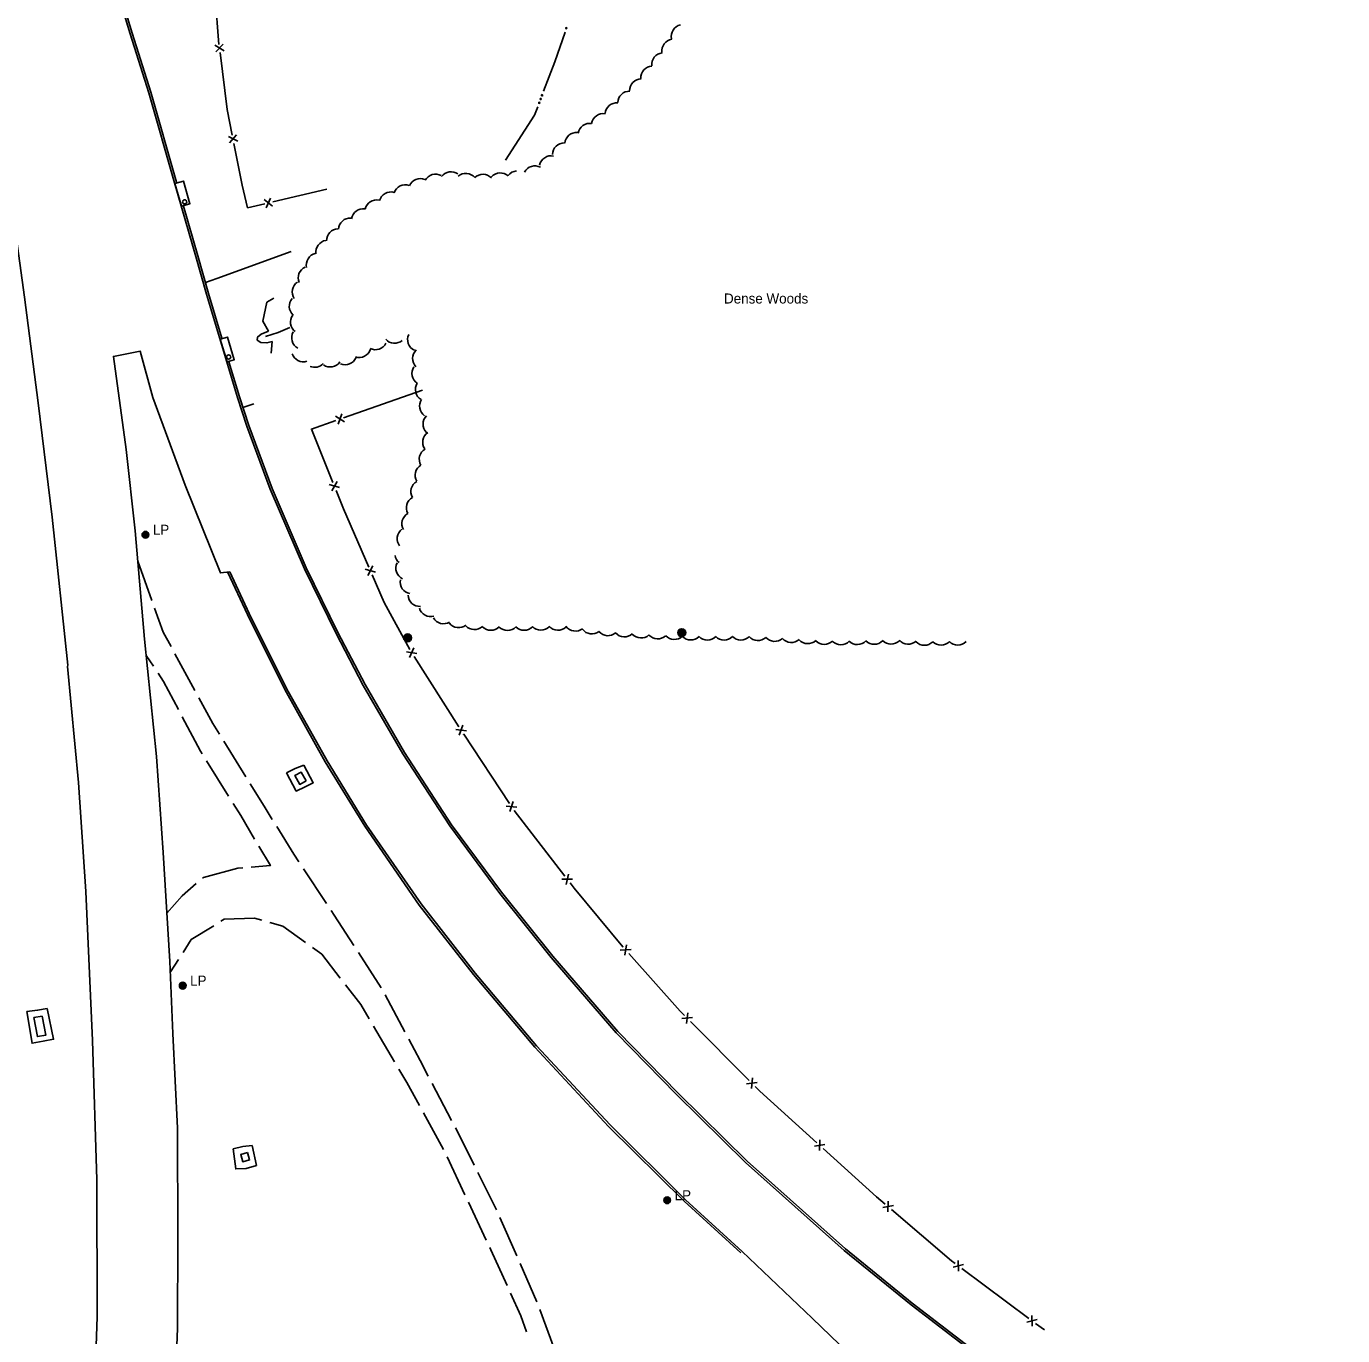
# Model space of a CAD drawing. Extents: x 2402803 to 2427059, y 6985292 to 6997652.
# Drawn here: x 2410720 to 2411350, y 6993013 to 6993640 of the extents above; entities that cross this region are included whole.
import ezdxf

# ---------------------------------------------------------------- set-up
doc = ezdxf.new("R2010")
doc.units = 0
for name, color, linetype in [('p_drainage conc drain', 7, 'Continuous'), ('p_drainage riprap', 7, 'Continuous'), ('p_drainage water', 7, 'Continuous'), ('p_road - paved curb', 7, 'Continuous'), ('p_road bridge end', 7, 'Continuous'), ('p_road dirt road', 7, 'Continuous'), ('p_structure fence', 7, 'Continuous'), ('p_structure general', 7, 'Continuous'), ('p_utility manhole', 7, 'Continuous'), ('p_veg woods', 7, 'Continuous')]:
    doc.layers.add(name, color=color, linetype=linetype)

msp = doc.modelspace()

# ---------------------------------------------------------------- linework, layer by layer
at = {"layer": 'p_drainage conc drain'}
for points in [[(2410835.86, 6993493.62), (2410833.12, 6993498.4), (2410835.12, 6993507.49), (2410838.52, 6993509.4)], [(2410837.63, 6993488.72), (2410837.17, 6993483.12)], [(2410852.84, 6993285.86), (2410857.34, 6993277.38), (2410853.46, 6993275.46), (2410849.22, 6993273.41), (2410844.47, 6993282.22)], [(2410844.47, 6993282.22), (2410848.72, 6993284.28), (2410852.84, 6993285.86)], [(2410720.19, 6993167.95), (2410722.65, 6993152.66), (2410727.99, 6993153.73), (2410732.93, 6993154.56), (2410729.81, 6993169.28)], [(2410729.81, 6993169.28), (2410725.31, 6993168.47), (2410720.19, 6993167.95)], [(2410830.17, 6993094.2), (2410825.12, 6993092.72), (2410820.22, 6993092.51), (2410819.02, 6993102.08), (2410823.61, 6993103.23), (2410827.99, 6993103.76)], [(2410827.99, 6993103.76), (2410830.17, 6993094.2)]]:
    msp.add_lwpolyline(points, dxfattribs=at)
at = {"layer": 'p_drainage riprap'}
for points in [[(2410805.65, 6993516.91), (2410811.16, 6993518.92), (2410846.77, 6993531.8)], [(2410823.66, 6993457.11), (2410828.9, 6993458.89)]]:
    msp.add_lwpolyline(points, dxfattribs=at)
at = {"layer": 'p_drainage water'}
for points in [[(2410967.69, 6993608.6), (2410973.01, 6993622.62), (2410977.91, 6993636.8)], [(2410949.42, 6993575.5), (2410963.32, 6993597.07), (2410964.86, 6993601.12)], [(2410834.39, 6993491.04), (2410840.51, 6993492.98), (2410846.15, 6993495.37)]]:
    msp.add_lwpolyline(points, dxfattribs=at)
for centre in [(2410978.57, 6993638.69), (2410966.25, 6993604.79), (2410966.93, 6993606.58), (2410965.57, 6993602.99)]:
    msp.add_circle(centre, 0.3, dxfattribs=at)
at = {"layer": 'p_road - paved curb'}
for points in [[(2410741.61, 6992826.02), (2410747.83, 6992895.57), (2410751.8, 6992961.6), (2410753.85, 6993021.62), (2410753.73, 6993087.24), (2410751.62, 6993154), (2410748.47, 6993225.36), (2410744.95, 6993277.46), (2410739.67, 6993333.06), (2410739.78, 6993333.65), (2410732.25, 6993404.63), (2410725.5, 6993459.29), (2410718.97, 6993509.93), (2410712.31, 6993558.83), (2410703.69, 6993610.23), (2410694.62, 6993664.96), (2410685.34, 6993713.02), (2410674.64, 6993766.89), (2410663.97, 6993813.71), (2410654.74, 6993854.5), (2410643.68, 6993898.31), (2410630.27, 6993950.34), (2410611.59, 6994020.31)], [(2410661.41, 6994010.21), (2410658.86, 6994008.83), (2410658.3, 6994005.38), (2410671.11, 6993965.12), (2410686.11, 6993913.59), (2410701.48, 6993863.45), (2410717.93, 6993809.81), (2410736.78, 6993747.65), (2410754.03, 6993691.08), (2410770.61, 6993636.29), (2410779.54, 6993608.03), (2410791.76, 6993564.95), (2410791.86, 6993564.61)], [(2410753.07, 6993690.79), (2410769.65, 6993635.99), (2410778.58, 6993607.74), (2410790.8, 6993564.67), (2410801.1, 6993529.39), (2410806.19, 6993511.31), (2410821.06, 6993461.9), (2410825.5, 6993448.18), (2410836.65, 6993417.97), (2410853.06, 6993379.91), (2410868.25, 6993348.87), (2410881.28, 6993323.93), (2410900.22, 6993291.3), (2410922.8, 6993256.76), (2410946.76, 6993224.37), (2410971.31, 6993193.78), (2411002.4, 6993157.69), (2411031.33, 6993128.1), (2411064.44, 6993095.5), (2411111.65, 6993053.47), (2411143.64, 6993027.42), (2411189.66, 6992992.15)], [(2410795.11, 6993553.47), (2410802.06, 6993529.67), (2410807.15, 6993511.59), (2410813.55, 6993490.32)], [(2410817.36, 6993378.43), (2410812.85, 6993377.9), (2410795.95, 6993419.89), (2410780.43, 6993461.86), (2410774.5, 6993484), (2410761.64, 6993481.57), (2410767.66, 6993436.99), (2410772.02, 6993397.98), (2410776.55, 6993346.19), (2410782.25, 6993289.92), (2410785.37, 6993243.96), (2410788.68, 6993191.83), (2410790.11, 6993157.32), (2410792.36, 6993112.02), (2410792.46, 6993059.64), (2410792.31, 6993016.31), (2410790.42, 6992966.33), (2410788.49, 6992929.02), (2410785.78, 6992887.8), (2410782.14, 6992848.18), (2410779.61, 6992824.88)], [(2410816.97, 6993478.96), (2410822.01, 6993462.2), (2410826.45, 6993448.51), (2410837.58, 6993418.34), (2410853.97, 6993380.33), (2410869.14, 6993349.32), (2410882.16, 6993324.41), (2410901.07, 6993291.82), (2410923.62, 6993257.33), (2410947.55, 6993224.98), (2410972.08, 6993194.42), (2411003.14, 6993158.37), (2411032.04, 6993128.81), (2411065.12, 6993096.23), (2411112.3, 6993054.23), (2411144.26, 6993028.2), (2411190.25, 6992992.96), (2411245.2, 6992955.15), (2411285.15, 6992929.75), (2411324.33, 6992906.35), (2411350.4, 6992892.78)], [(2411062.09, 6993052.3), (2411035.01, 6993077), (2410998.76, 6993112.87), (2410963.47, 6993150.82), (2410934.04, 6993185.62), (2410908.13, 6993218.83), (2410882, 6993256.56), (2410863.1, 6993287.37), (2410843.65, 6993322.06), (2410825.78, 6993357.96), (2410816.43, 6993378.01)], [(2411062.76, 6993053.04), (2411035.7, 6993077.73), (2410999.48, 6993113.57), (2410964.22, 6993151.48), (2410934.82, 6993186.25), (2410908.94, 6993219.42), (2410882.84, 6993257.11), (2410863.96, 6993287.88), (2410844.53, 6993322.53), (2410826.68, 6993358.39), (2410817.34, 6993378.43)], [(2411317.49, 6992824.55), (2411281.06, 6992855.57), (2411247.54, 6992884.91), (2411216.91, 6992910.99), (2411184.48, 6992939.55), (2411159.27, 6992962.45), (2411126.67, 6992991.89), (2411096.26, 6993021.03), (2411062.76, 6993053.04)]]:
    msp.add_lwpolyline(points, dxfattribs=at)
at = {"layer": 'p_road bridge end'}
for points in [[(2410794.18, 6993553.47), (2410791.01, 6993564.31), (2410795.12, 6993565.51), (2410798.29, 6993554.67)], [(2410816.04, 6993478.94), (2410812.8, 6993489.74), (2410816.24, 6993490.77), (2410819.48, 6993479.97)], [(2410853.86, 6993278.25), (2410851.51, 6993282.53), (2410848.53, 6993280.89), (2410850.88, 6993276.61)], [(2410727.5, 6993165.72), (2410729.24, 6993156.61), (2410725.23, 6993155.85), (2410723.49, 6993164.96)], [(2410825.89, 6993100.29), (2410826.85, 6993096.85), (2410823.52, 6993095.92), (2410822.56, 6993099.36)]]:
    msp.add_lwpolyline(points, close=True, dxfattribs=at)
msp.add_lwpolyline([(2410835.86, 6993493.62), (2410832.44, 6993492.2), (2410830.63, 6993490.8), (2410830.43, 6993489.33), (2410832.24, 6993488.24), (2410835.12, 6993488.03), (2410837.63, 6993488.72)], dxfattribs=at)
at = {"layer": 'p_road dirt road'}
for p, q in [((2410773.28, 6993383.58), (2410780, 6993364.75)), ((2410791.1, 6993339.13), (2410800.64, 6993321.56)), ((2410780.75, 6993333.2), (2410777.35, 6993338.28)), ((2410814.51, 6993297.25), (2410825.04, 6993280.25)), ((2410816.78, 6993270.94), (2410806.18, 6993287.9)), ((2410852.69, 6993236.23), (2410863.68, 6993219.53)), ((2410878.92, 6993196.06), (2410889.79, 6993179.28)), ((2410792.79, 6993192.81), (2410788.96, 6993186.8)), ((2410891.84, 6993175.85), (2410901.17, 6993158.19)), ((2410896.32, 6993143.7), (2410886.17, 6993160.91)), ((2410914.22, 6993133.44), (2410923.53, 6993115.74)), ((2410919.66, 6993101.81), (2410910.07, 6993119.33)), ((2410930, 6993080.16), (2410921.54, 6993098.28)), ((2410936.2, 6993090.79), (2410945.12, 6993072.9)), ((2410940.15, 6993058.42), (2410931.69, 6993076.54)), ((2410946.76, 6993069.26), (2410954.76, 6993050.93)), ((2410956.36, 6993047.26), (2410964.36, 6993028.94)), ((2410965.79, 6993025.2), (2410972.7, 6993006.44))]:
    msp.add_line(p, q, dxfattribs=at)
for points in [[(2410781.35, 6993360.98), (2410785.42, 6993349.58), (2410789.19, 6993342.64)], [(2410792.74, 6993312.45), (2410785.6, 6993325.95), (2410782.97, 6993329.88)], [(2410802.55, 6993318.04), (2410809.18, 6993305.84), (2410812.4, 6993300.65)], [(2410804.06, 6993291.29), (2410803.26, 6993292.58), (2410794.61, 6993308.92)], [(2410827.15, 6993276.85), (2410833.77, 6993266.17), (2410837.7, 6993259.87)], [(2410829.24, 6993250.44), (2410822.56, 6993261.69), (2410818.9, 6993267.55)], [(2410839.82, 6993256.47), (2410848.04, 6993243.29), (2410850.49, 6993239.57)], [(2410827.59, 6993237.02), (2410836.78, 6993237.73), (2410831.28, 6993247)], [(2410804.34, 6993231.7), (2410804.72, 6993232.03), (2410821.15, 6993236.52), (2410823.6, 6993236.71)], [(2410787.25, 6993214.99), (2410794.52, 6993223.33), (2410801.3, 6993229.11)], [(2410832.62, 6993211.63), (2410829.15, 6993212.62), (2410814.62, 6993212.03), (2410813.05, 6993211.06)], [(2410865.88, 6993216.19), (2410867.3, 6993214.04), (2410867.3, 6993214.01), (2410876.75, 6993199.42)], [(2410809.65, 6993208.97), (2410798.84, 6993202.3), (2410794.94, 6993196.17)], [(2410853.67, 6993200.86), (2410842.74, 6993208.74), (2410836.47, 6993210.53)], [(2410870.27, 6993183.87), (2410861.38, 6993195.3), (2410856.91, 6993198.52)], [(2410884.14, 6993164.36), (2410880.07, 6993171.26), (2410872.72, 6993180.71)], [(2410903.04, 6993154.65), (2410908.46, 6993144.4), (2410912.36, 6993136.98)], [(2410908.15, 6993122.84), (2410902.15, 6993133.81), (2410898.35, 6993140.25)], [(2410925.39, 6993112.21), (2410928, 6993107.24), (2410934.42, 6993094.37)], [(2410950.17, 6993036.62), (2410942.32, 6993053.76), (2410941.84, 6993054.8)], [(2410959.53, 6993014.55), (2410956.8, 6993022.13), (2410951.83, 6993032.98)]]:
    msp.add_lwpolyline(points, dxfattribs=at)
at = {"layer": 'p_structure fence'}
for p, q in [((2410810.24, 6993630.53), (2410814.61, 6993627.86)), ((2410810.64, 6993627.35), (2410814.21, 6993631.03)), ((2410816.66, 6993586.91), (2410821.21, 6993584.55)), ((2410817.28, 6993583.78), (2410820.58, 6993587.69)), ((2410837.96, 6993555.55), (2410863.87, 6993561.62)), ((2410837.83, 6993553.49), (2410833.8, 6993556.66)), ((2410834.72, 6993552.76), (2410836.92, 6993557.39)), ((2410909.58, 6993465.45), (2410871.85, 6993452.19)), ((2410867.99, 6993452.92), (2410872.34, 6993450.2)), ((2410871.01, 6993453.98), (2410869.32, 6993449.14)), ((2410866.21, 6993417.21), (2410868.73, 6993421.67)), ((2410865.02, 6993420.18), (2410869.92, 6993418.7)), ((2410882.23, 6993379.63), (2410887.18, 6993378.29)), ((2410883.51, 6993376.7), (2410885.9, 6993381.22)), ((2410901.93, 6993340.14), (2410906.97, 6993339.25)), ((2410903.46, 6993337.33), (2410905.44, 6993342.06)), ((2410905.67, 6993337.87), (2410927.12, 6993304.12)), ((2410925.56, 6993302.89), (2410930.66, 6993302.33)), ((2410927.28, 6993300.19), (2410928.94, 6993305.04)), ((2410949.77, 6993266.26), (2410954.87, 6993265.79)), ((2410951.54, 6993263.59), (2410953.11, 6993268.46)), ((2410978.39, 6993228.72), (2410979.6, 6993233.7)), ((2410976.44, 6993231.25), (2410981.56, 6993231.17)), ((2411006.55, 6993194.82), (2411007.4, 6993199.87)), ((2411004.41, 6993197.21), (2411009.53, 6993197.49)), ((2411033.89, 6993164.47), (2411038.98, 6993165.02)), ((2411036.14, 6993162.2), (2411036.73, 6993167.29)), ((2411037.96, 6993163.17), (2411066.16, 6993134.8)), ((2411064.9, 6993133.27), (2411070, 6993133.82)), ((2411067.16, 6993131), (2411067.74, 6993136.09)), ((2411099.73, 6993101.28), (2411100.04, 6993106.4)), ((2411097.36, 6993103.43), (2411102.42, 6993104.25)), ((2411130.15, 6993074.01), (2411135.18, 6993074.98)), ((2411132.58, 6993071.93), (2411132.74, 6993077.05)), ((2411166.37, 6993043.57), (2411166.2, 6993048.69)), ((2411163.81, 6993045.49), (2411168.77, 6993046.78)), ((2411168.03, 6993044.79), (2411200.09, 6993020.88)), ((2411199.08, 6993019.18), (2411204.03, 6993020.47)), ((2411201.64, 6993017.26), (2411201.47, 6993022.38)), ((2411203.31, 6993018.49), (2411207.57, 6993015.49))]:
    msp.add_line(p, q, dxfattribs=at)
for points in [[(2410809.1, 6993670.85), (2410811.92, 6993632.96), (2410812.17, 6993630.97)], [(2410812.67, 6993627.01), (2410816.1, 6993599.85), (2410818.55, 6993587.49)], [(2410819.33, 6993583.57), (2410823.3, 6993563.59), (2410825.85, 6993552.71), (2410834.07, 6993554.64)], [(2410868.08, 6993450.86), (2410856.45, 6993446.77), (2410866.77, 6993421.1)], [(2410868.26, 6993417.39), (2410871.8, 6993408.59), (2410883.96, 6993380.6)], [(2410885.55, 6993376.93), (2410891.26, 6993363.79), (2410903.56, 6993341.26)], [(2410929.26, 6993300.74), (2410929.36, 6993300.59), (2410929.47, 6993300.61), (2410951.31, 6993267.51)], [(2410953.51, 6993264.17), (2410953.55, 6993264.11), (2410977.87, 6993232.62)], [(2410980.31, 6993229.46), (2410982.25, 6993226.95), (2411005.59, 6993198.85), (2411005.75, 6993198.67)], [(2411008.41, 6993195.69), (2411033.11, 6993168.05), (2411035.14, 6993166)], [(2411068.98, 6993131.96), (2411071.19, 6993129.74), (2411098.53, 6993105.02)], [(2411101.5, 6993102.34), (2411127.16, 6993079.15), (2411131.27, 6993075.64)], [(2411134.32, 6993073.04), (2411163.09, 6993048.48), (2411164.83, 6993047.18)]]:
    msp.add_lwpolyline(points, dxfattribs=at)
at = {"layer": 'p_structure general'}
for centre in [(2410795.76, 6993555.53), (2410816.79, 6993481.29)]:
    msp.add_circle(centre, 1, dxfattribs=at)
at = {"layer": 'p_utility manhole'}
for centre, radius in [((2410776.92, 6993396.16), 1.6), ((2410776.92, 6993396.16), 1.3), ((2410776.92, 6993396.16), 1), ((2410776.92, 6993396.16), 0.539), ((2410776.92, 6993396.16), 0.192), ((2410902.49, 6993346.81), 1.9), ((2410902.49, 6993346.81), 1.44), ((2410902.49, 6993346.81), 0.973), ((2410902.49, 6993346.81), 0.539), ((2410902.49, 6993346.81), 0.192), ((2411033.85, 6993349.24), 1.9), ((2411033.85, 6993349.24), 1.44), ((2411033.85, 6993349.24), 0.973), ((2411033.85, 6993349.24), 0.539), ((2411033.85, 6993349.24), 0.192), ((2410794.79, 6993180.25), 1.6), ((2410794.79, 6993180.25), 1.3), ((2410794.79, 6993180.25), 1), ((2410794.79, 6993180.25), 0.539), ((2410794.79, 6993180.25), 0.192), ((2411026.87, 6993077.5), 1.6), ((2411026.87, 6993077.5), 1.3), ((2411026.87, 6993077.5), 1), ((2411026.87, 6993077.5), 0.539), ((2411026.87, 6993077.5), 0.192)]:
    msp.add_circle(centre, radius, dxfattribs=at)
at = {"layer": 'p_veg woods'}
for centre, start, end in [((2411034.45, 6993634.75), 102.3138, 192.3138), ((2411029.94, 6993627.8), 98.27594, 188.27594), ((2411025.06, 6993621.26), 95.88731, 185.88731), ((2411019.87, 6993614.95), 93.44793, 183.44793), ((2411014.48, 6993608.79), 90.79642, 180.79642), ((2411008.79, 6993602.88), 87.79252, 177.79252), ((2410996.25, 6993592.17), 80.69003, 170.69003), ((2411002.69, 6993597.3), 84.01939, 174.01939), ((2410989.76, 6993587.5), 80.69003, 170.69003), ((2410983.38, 6993583.06), 84.10501, 174.10501), ((2410977.55, 6993578.11), 89.10675, 179.10675), ((2410963.45, 6993567.14), 61.74151, 151.74151), ((2410971.25, 6993571.96), 77.99186, 167.99186), ((2410908.66, 6993561.05), 67.73202, 157.73202), ((2410915.93, 6993563.16), 61.46817, 151.46817), ((2410923.33, 6993564.32), 54.00821, 144.00821), ((2410930.38, 6993563.53), 40.33492, 130.33492), ((2410938.62, 6993563.09), 43.98662, 133.98662), ((2410946.89, 6993563.73), 48.17415, 138.17415), ((2410955.12, 6993564.71), 93.95583, 142.21756), ((2410894.52, 6993554.64), 74.46337, 164.46337), ((2410901.5, 6993558.1), 71.53734, 161.53734), ((2410887.76, 6993550.86), 78.34064, 168.34064), ((2410875.06, 6993542.17), 87.10179, 177.10179), ((2410881.23, 6993546.59), 81.15438, 171.15438), ((2410869.37, 6993537.04), 92.03708, 182.03708), ((2410864.23, 6993531.5), 98.46988, 188.46988), ((2410859.65, 6993525.39), 103.73481, 193.73481), ((2410855.74, 6993519.13), 113.10223, 203.10223), ((2410852.91, 6993512.42), 123.78688, 213.78688), ((2410851.48, 6993505.52), 137.86548, 227.86548), ((2410852.03, 6993497.95), 143.36625, 233.36625), ((2410852.65, 6993490.49), 150.89121, 240.89121), ((2410908.15, 6993489.64), 154.9023, 244.9023), ((2410879.34, 6993486.66), 252.35584, 342.35584), ((2410887.07, 6993490.4), 243.88733, 333.88733), ((2410896.29, 6993493.49), 220.91259, 310.91259), ((2410910.58, 6993480.54), 133.82808, 223.82808), ((2410852.58, 6993484.58), 197.80002, 287.80002), ((2410858.04, 6993481.97), 246.61819, 316.68064), ((2410865.46, 6993482.14), 235.06956, 325.06956), ((2410872.61, 6993483.21), 246.90779, 336.90779), ((2410910.21, 6993473.42), 146.7358, 236.7358), ((2410911.87, 6993465.74), 148.7272, 238.7272), ((2410913.88, 6993457.76), 145.44907, 235.44907), ((2410915.56, 6993449.15), 134.68833, 224.68833), ((2410915.39, 6993440.48), 125.01561, 215.01561), ((2410913.76, 6993432.34), 120.60099, 210.60099), ((2410911.75, 6993424.57), 120.08634, 210.08634), ((2410909.7, 6993416.82), 119.73683, 209.73683), ((2410907.59, 6993409.08), 119.18031, 209.18031), ((2410905.41, 6993401.42), 119.53397, 209.53397), ((2410903.17, 6993394.3), 127.55921, 217.55921), ((2410902.08, 6993387.19), 190.29084, 229.53933), ((2410902.54, 6993380.15), 153.63581, 243.63581), ((2410904.6, 6993373.5), 169.48463, 259.48463), ((2410908.38, 6993367.48), 183.11013, 273.11013), ((2410913.56, 6993362.62), 196.45778, 286.45778), ((2410919.72, 6993359.21), 210.57175, 300.57175), ((2410926.96, 6993357.34), 218.05817, 308.05817), ((2410934.59, 6993356.37), 222.26738, 312.26738), ((2410942.43, 6993356.05), 224.3289, 314.3289), ((2410950.32, 6993355.99), 225.62553, 315.62553), ((2410958.31, 6993356.07), 225.58689, 315.58689), ((2410966.37, 6993356.14), 224.55226, 314.55226), ((2410974.57, 6993356.08), 221.71019, 311.71019), ((2410982.92, 6993355.68), 216.64515, 306.64515), ((2410990.75, 6993354.34), 217.41418, 307.41418), ((2410998.46, 6993353.45), 220.81844, 310.81844), ((2411006.41, 6993352.89), 221.26745, 311.26745), ((2411014.33, 6993352.37), 222.15268, 312.15268), ((2411022.29, 6993351.97), 222.59736, 312.59736), ((2411030.23, 6993351.65), 223.42734, 313.42734), ((2411038.14, 6993351.43), 224.6837, 314.6837), ((2411046.11, 6993351.39), 225.07241, 315.07241), ((2411054.12, 6993351.4), 224.87109, 314.87109), ((2411062.2, 6993351.38), 223.76377, 313.76377), ((2411070.33, 6993351.18), 221.88792, 311.88792), ((2411078.37, 6993350.74), 221.18434, 311.18434), ((2411086.35, 6993350.21), 221.18434, 311.18434), ((2411094.24, 6993349.65), 222.47776, 312.47776), ((2411102.14, 6993349.29), 223.79737, 313.79737), ((2411110.02, 6993349.14), 225.56327, 315.56327), ((2411118, 6993349.22), 225.82249, 315.82249), ((2411126, 6993349.34), 225.82249, 315.82249), ((2411134.08, 6993349.44), 224.64649, 314.64649), ((2411142.31, 6993349.41), 221.40617, 311.40617), ((2411150.02, 6993348.89), 225.32098, 315.32098), ((2411158.02, 6993348.93), 225.32098, 315.32098), ((2411166.02, 6993348.98), 225.32098, 315.32098)]:
    msp.add_arc(centre, 5.65, start, end, dxfattribs=at)

# ---------------------------------------------------------------- texts
at = {"layer": 'p_utility manhole'}
for p in [(2410776.92, 6993396.16), (2410794.79, 6993180.25), (2411026.87, 6993077.5)]:
    msp.add_text('  LP', height=4.8, dxfattribs=at).set_placement(p)
at = {"layer": 'p_veg woods'}
msp.add_text('Dense Woods', height=4.8, dxfattribs=at).set_placement((2411054.09, 6993506.87))

doc.saveas('drawing.dxf')
